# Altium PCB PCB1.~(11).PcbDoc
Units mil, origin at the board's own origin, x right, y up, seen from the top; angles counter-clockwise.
Board outline 1890 x 1900 mil, 2 copper layers (Top Layer, Bottom Layer); 27 components, 29 nets, 115 pads, 0 vias.
Unrouted connection lines stored in the file: 71.
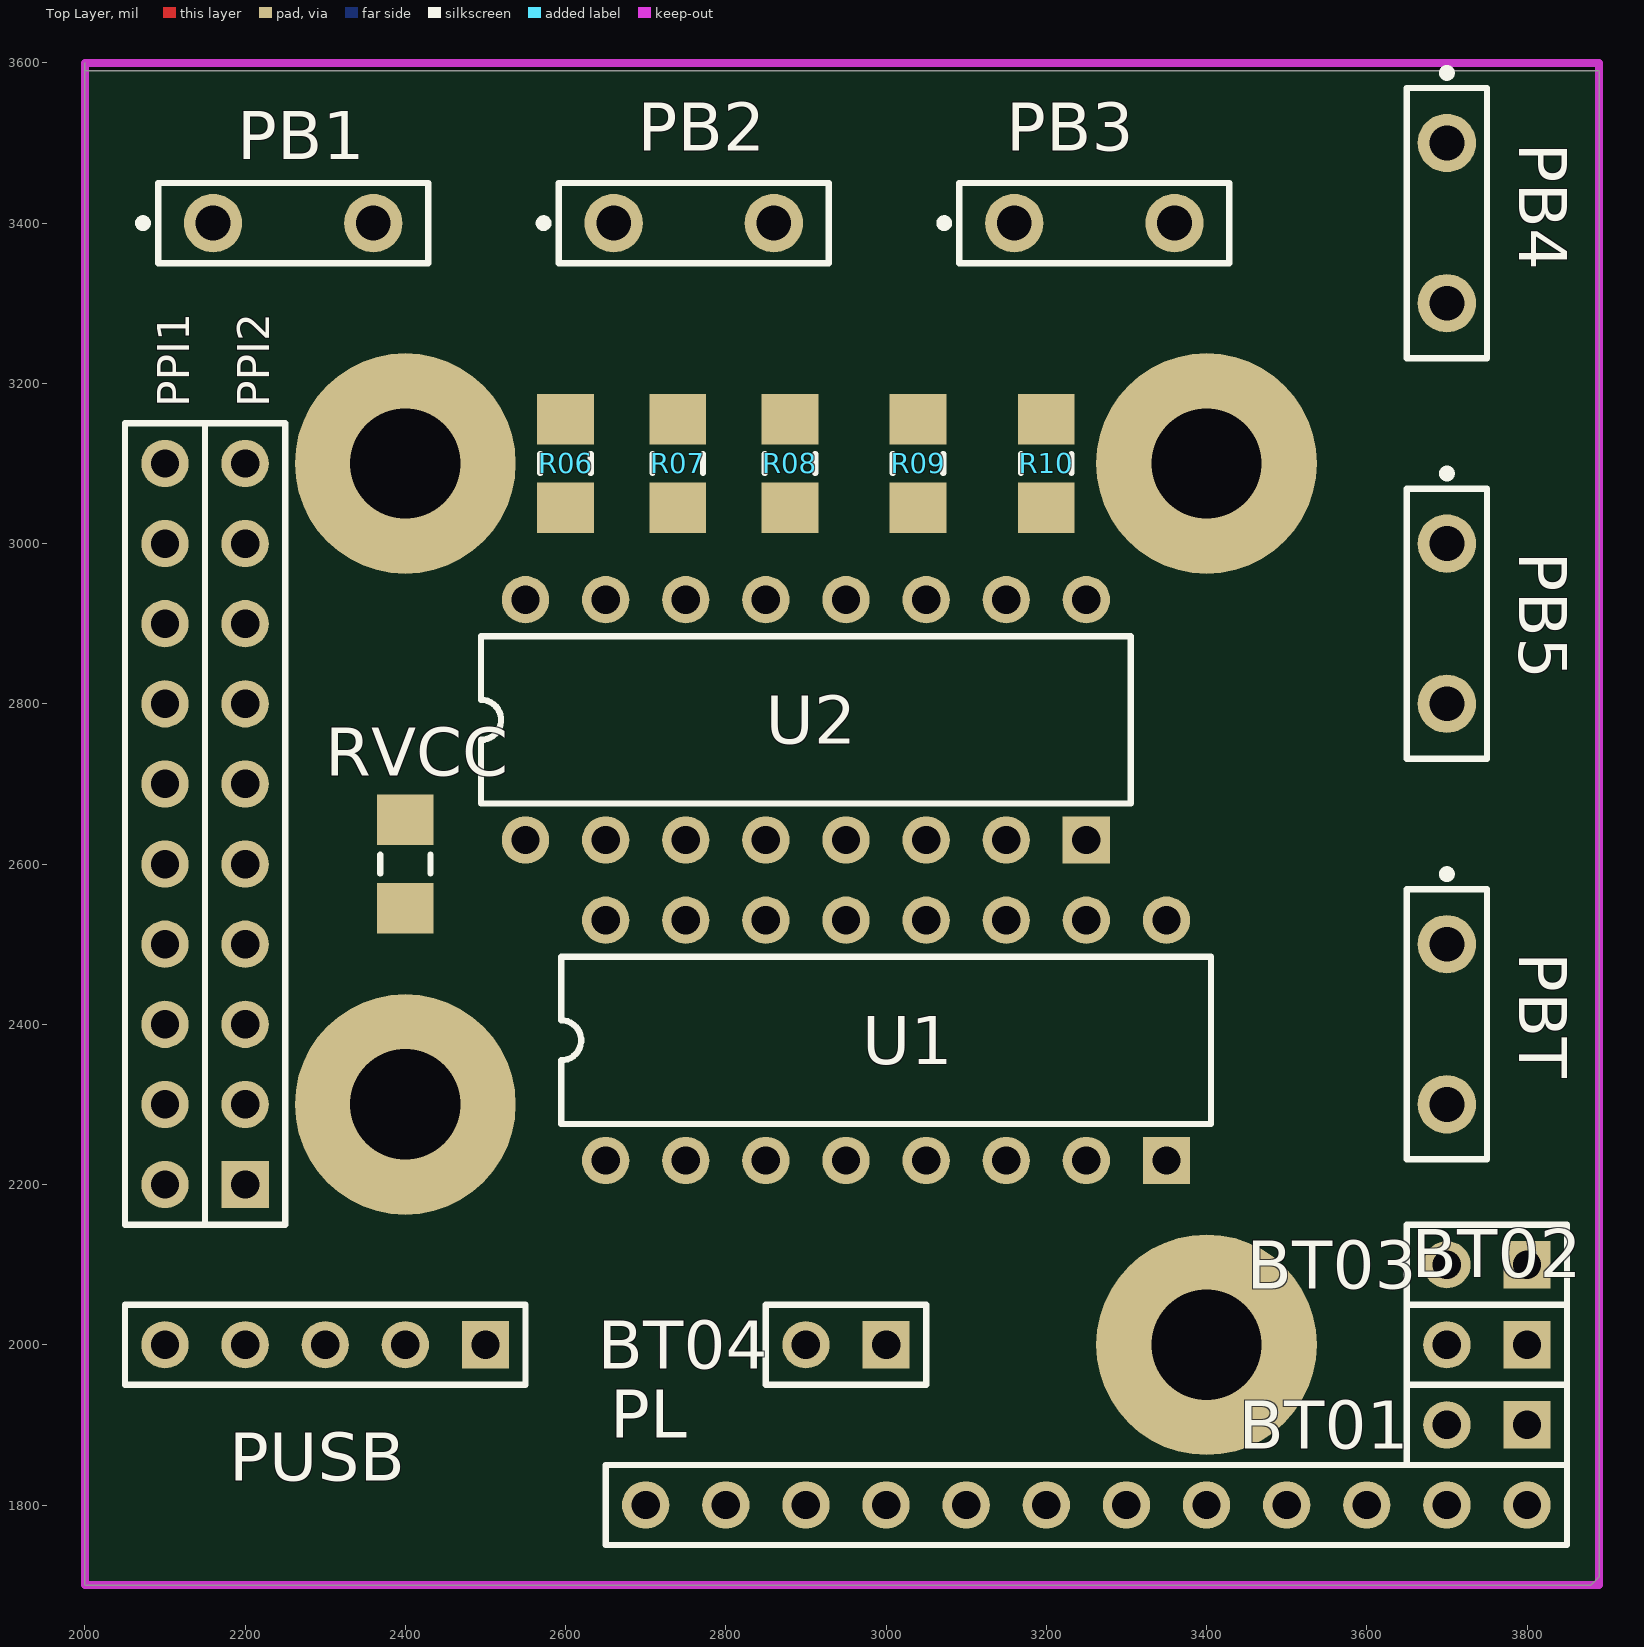
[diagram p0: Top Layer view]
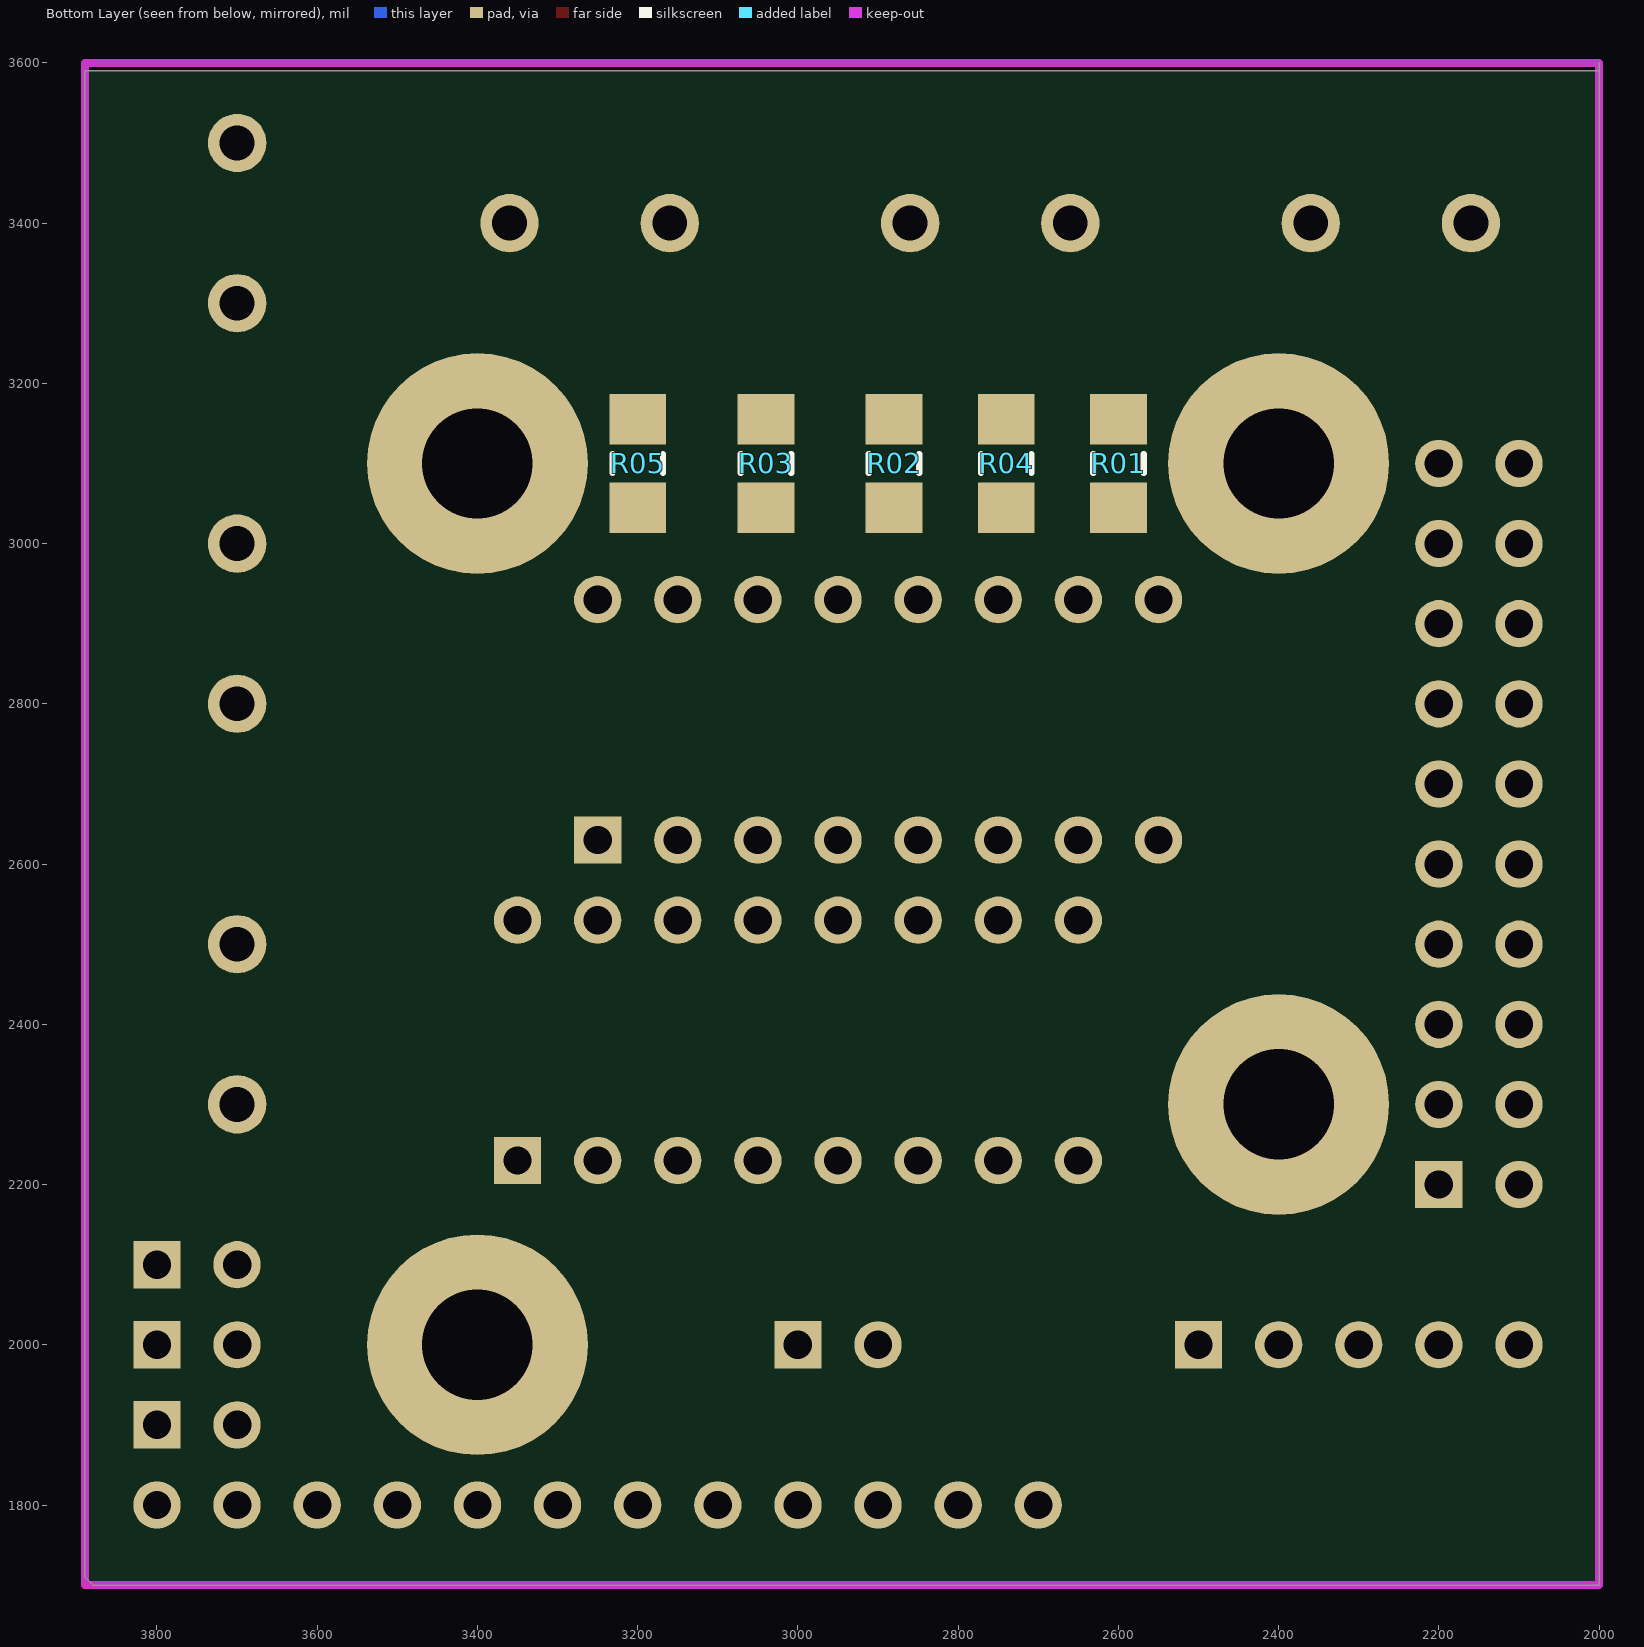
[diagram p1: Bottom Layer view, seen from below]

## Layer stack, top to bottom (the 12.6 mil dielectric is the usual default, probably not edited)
Top Layer: signal copper 1.4
Dielectric: dielectric 12.6, FR-4, Dk 4.8
Bottom Layer: signal copper 1.4

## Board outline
2010,3590 3890,3590 3890,1710 3880,1700 2000,1700 2000,3600 2000,3590

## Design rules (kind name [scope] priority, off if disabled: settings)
Clearance [All] p1: gap=10
ComponentClearance [All] p1: gap=10 collisioncheckmode=3 verticalgap=10
PolygonConnect [All] p1: connectstyle=Relief reliefconductorwidth=10 reliefentries=4 polygonreliefangle="90 Angle"
RoomDefinition Sheet1 [InComponentClass('Sheet1')] p1: confinementstyle=ConfineIn formatcopy=TRUE lockcomponents=FALSE outline 0,0 2000,0 2000,1000 0,1000
RoutingVias [All] p1: holewidth=28 width=50 viastyle="Through Hole" minholewidth=28 minwidth=50 maxholewidth=28 maxwidth=50
SolderMaskExpansion [All] p1: expansion=4
TestPointUsage [All] p1: valid=0 allowmultiple=FALSE
Testpoint [All] p1: side=15 testpointundercomponent=TRUE minsize=40 maxsize=100 preferedsize=60 minholesize=0 maxholesize=40 preferedholesize=32 testpointgrid=1 style=1023 order=0123456789
Width Width_2 [All] p1: maxlimit=30 minlimit=15 preferedwidth=20
Width Width_1 [InNet('VCC')] p2: maxlimit=30 minlimit=20 preferedwidth=30
Width [InNet('GND')] p3: maxlimit=30 minlimit=20 preferedwidth=30
18 further rules are at their usual default settings.

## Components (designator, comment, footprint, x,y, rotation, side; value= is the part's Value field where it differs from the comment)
BT01 "Header 2" HDR1X2 3800,1900 r180 top
BT02 "Header 2" HDR1X2 3800,2000 r180 top
BT03 "Header 2" HDR1X2 3800,2100 r180 top
BT04 "Header 2" HDR1X2 3000,2000 r180 top
PB1 "Header 2" SPST-2 2260,3400 r0 top
PB2 "Header 2" SPST-2 2760,3400 r0 top
PB3 "Header 2" SPST-2 3260,3400 r0 top
PB4 "Header 2" SPST-2 3700,3400 r270 top
PB5 "Header 2" SPST-2 3700,2900 r270 top
PBT "Header 2" SPST-2 3700,2400 r270 top
PL "Header 12" HDR1X12 2700,1800 r0 top
PPI1 "Header 10" HDR1X10#1 2100,3100 r270 top
PPI2 "Header 10" HDR1X10#2 2200,3100 r270 top
PUSB "Header 5" HDR1X5 2100,2000 r0 top
R01 "Res1" 3216[1206] 2600,3100 r270 bottom
R02 "Res1" 3216[1206] 2880,3100 r270 bottom
R03 "Res1" 3216[1206] 3040,3100 r270 bottom
R04 "Res1" 3216[1206] 2740,3100 r270 bottom
R05 "Res1" 3216[1206] 3200,3100 r270 bottom
R06 "Res1" 3216[1206] 2600,3100 r270 top
R07 "Res1" 3216[1206] 2740,3100 r270 top
R08 "Res1" 3216[1206] 2880,3100 r270 top
R09 "Res1" 3216[1206] 3040,3100 r270 top
R10 "Res1" 3216[1206] 3200,3100 r270 top
RVCC "Res1" 3216[1206] 2400,2600 r90 top
U1 "SN74HC138D" DIP-16 3000,2380 r0 top
U2 "SN74HC138D" DIP-16 2900,2780 r0 top

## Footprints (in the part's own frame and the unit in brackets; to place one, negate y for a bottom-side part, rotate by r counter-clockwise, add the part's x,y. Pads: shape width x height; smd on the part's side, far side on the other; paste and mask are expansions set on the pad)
3216[1206] [mm] "Chip Resistor; Body 3.2 x 1.6 mm (LxW typ)"
  rect 1.6x1.8 smd: 1(-1.4,0) 2(1.4,0)
  silkscreen extent -0.3,-0.8 0.3,0.8
DIP-16 [mm] "DIP; 16 Leads; Row Spacing 7.62 mm; Pitch 2.54 mm"
  round 1.5 hole 0.9: 1(-8.89,-3.81) 2(-6.35,-3.81) 3(-3.81,-3.81) 4(-1.27,-3.81) 5(1.27,-3.81) 6(3.81,-3.81) 7(6.35,-3.81) 9(8.89,3.81) 10(6.35,3.81) 11(3.81,3.81) 12(1.27,3.81) 13(-1.27,3.81) 14(-3.81,3.81) 15(-6.35,3.81) 16(-8.89,3.81)
  rect 1.5x1.5 hole 0.9: 8(8.89,-3.81)
  silkscreen extent -10.3,-2.65 10.3,2.65
HDR1X2 [mm] "Connector; Header; 2 Position"
  rect 1.5x1.5 hole 0.9: 1(0,0)
  round 1.5 hole 0.9: 2(2.54,0)
  silkscreen extent -1.27,-1.27 3.81,1.27
HDR1X5 [mm] "Connector; Header; 5 Position"
  round 1.5 hole 0.9: 1(0,0) 2(2.54,0) 3(5.08,0) 4(7.62,0)
  rect 1.5x1.5 hole 0.9: 5(10.16,0)
  silkscreen extent -1.27,-1.27 11.43,1.27
HDR1X10#1 [mm] "Connector; Header; 10 Position"
  round 1.5 hole 0.9: 1(0,0) 2(2.54,0) 3(5.08,0) 4(7.62,0) 5(10.16,0) 6(12.7,0) 7(15.24,0) 8(17.78,0) 9(20.32,0) 10(22.86,0)
  silkscreen extent -1.27,-1.27 24.13,1.27
HDR1X10#2 [mm] "Connector; Header; 10 Position"
  round 1.5 hole 0.9: 1(0,0) 2(2.54,0) 3(5.08,0) 4(7.62,0) 5(10.16,0) 6(12.7,0) 7(15.24,0) 8(17.78,0) 9(20.32,0)
  rect 1.5x1.5 hole 0.9: 10(22.86,0)
  silkscreen extent -1.27,-1.27 24.13,1.27
HDR1X12 [mm] "Connector; Header; 12 Position"
  round 1.5 hole 0.9: 1(0,0) 2(2.54,0) 3(5.08,0) 4(7.62,0) 5(10.16,0) 6(12.7,0) 7(15.24,0) 8(17.78,0) 9(20.32,0) 10(22.86,0) 11(25.4,0) 12(27.94,0)
  silkscreen extent -1.27,-1.27 29.21,1.27
SPST-2 [mm] "Circuit Breaker; 2 Leads"
  round 1.85 hole 1.1: 1(-2.54,0) 2(2.54,0)
  silkscreen extent -4.89,-1.27 4.28,1.27

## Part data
BT01 BT02 BT03 BT04 PB1 PB2 PB3 PB4 PB5 PBT: "Header, 2-Pin"
PL: "Header, 12-Pin"
PPI1 PPI2: "Header, 10-Pin"
PUSB: "Header, 5-Pin"
R01 R02 R03 R04 R05 R06 R07 R08 R09 R10 RVCC: "Resistor"
U1 U2: "3-Line to 8-Line Decoder / Demultiplexer"

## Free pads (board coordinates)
  round 275.59 hole 137.8: 0(3400,3100) 1(2400,3100) 3(3400,2000)
  round 275.59 hole 137.8 paste+0: 2(2400,2300)

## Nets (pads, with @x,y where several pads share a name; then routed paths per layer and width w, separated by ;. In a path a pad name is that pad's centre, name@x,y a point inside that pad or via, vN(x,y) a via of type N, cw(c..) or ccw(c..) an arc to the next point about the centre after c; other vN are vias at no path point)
GND: BT01.1 BT02.1 BT03.1 BT04.1 PBT.2 PL.12 PPI2.10 PUSB.5 R01.1 R02.1 R03.1 R04.1 R05.1 R06.1 R07.1 R08.1 R09.1 R10.1 U1.4 U1.5 U1.8 U2.4 U2.5 U2.8
NetPB1_1: PB1.1 PPI1.1 R01.2
NetPB1_2: PB1.2 PPI1.2 R02.2
NetPB2_1: PB2.1 PPI1.3 R03.2
NetPB2_2: PB2.2 PPI1.4 R04.2
NetPB3_1: PB3.1 PPI1.5 R05.2
NetPB3_2: PB3.2 PPI1.6 R06.2
NetPB4_1: PB4.1 PPI1.7 R07.2
NetPB4_2: PB4.2 PPI1.8 R08.2
NetPB5_1: PB5.1 PPI1.9 R09.2
NetPB5_2: PB5.2 PPI1.10 R10.2
NetPBT_1: PBT.1 RVCC.1
NetPL_1: PL.1 U1.15
NetPL_2: PL.2 U1.14
NetPL_3: PL.3 U1.13
NetPL_4: PL.4 U1.12
NetPL_5: PL.5 U1.11
NetPL_6: PL.6 U1.10
NetPL_7: PL.7 U1.9
NetPL_8: PL.8 U1.7
NetPL_9: PL.9 U2.15
NetPL_10: PL.10 U2.14
NetPPI2_1: PPI2.1 U1.1 U2.1
NetPPI2_2: PPI2.2 U1.2 U2.2
NetPPI2_3: PPI2.3 U1.3 U2.3
NetPPI2_4: PPI2.4 U1.6
NetPPI2_5: PPI2.5 U2.6
NetPPI2_7: PPI2.7 RVCC.2
VCC: BT01.2 BT02.2 BT03.2 BT04.2 PL.11 PPI2.9 PUSB.1 U1.16 U2.16
pads on no net: PPI2.6 PPI2.8 PUSB.2 PUSB.3 PUSB.4 U2.7 U2.9 U2.10 U2.11 U2.12 U2.13

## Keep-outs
Keep-Out Layer:
  lines w10: 2000,1700 2000,3600 3890,3600 3890,1700 2000,1700

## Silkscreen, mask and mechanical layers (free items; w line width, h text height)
Mechanical 1:
  lines w10: 2000,1700 2000,3600 3890,3600 3890,1710 2010,1710 2000,1700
